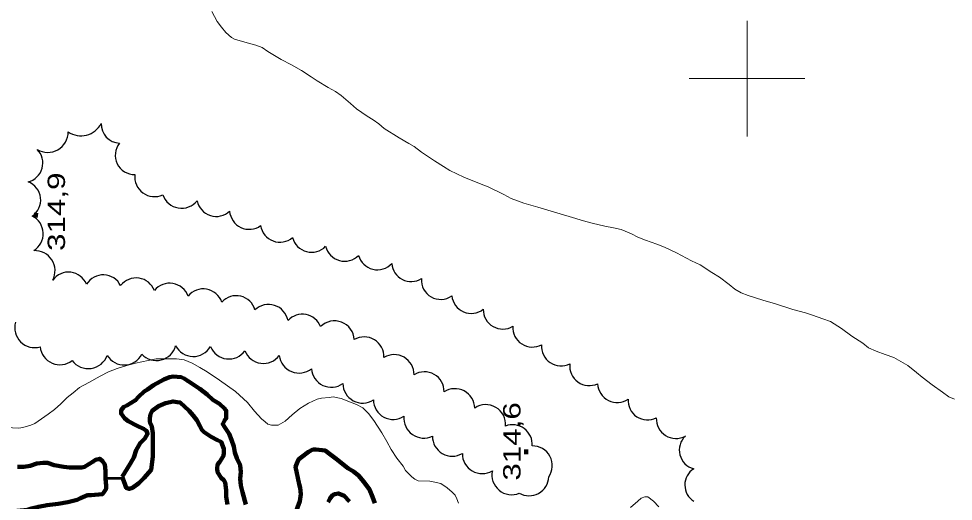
# Model space of a CAD drawing. Extents: x 240591 to 242335, y 5323482 to 5326937.
# Drawn here: x 240674 to 240835.7, y 5324326.9 to 5324410.4 of the extents above; entities that cross this region are included whole.
import ezdxf
from ezdxf.enums import TextEntityAlignment as Align

# ---------------------------------------------------------------- set-up
doc = ezdxf.new("R2010")
doc.units = 0
doc.header["$LTSCALE"] = 1.2
doc.linetypes.add('DASH_DOUBLE_DOT', pattern=[9.2, 5, -1.2, 0.3, -1.2, 0.3, -1.2])
doc.linetypes.add('LONG_DASHED', pattern=[7.5, 6, -1.5])
for name, color, linetype, lineweight in [('2', 7, 'Continuous', 13), ('3', 7, 'Continuous', 140), ('4', 7, 'DASH_DOUBLE_DOT', 53), ('44', 7, 'Continuous', 25), ('61', 7, 'Continuous', 13)]:
    doc.layers.add(name, color=color, linetype=linetype, lineweight=lineweight)

msp = doc.modelspace()

# ---------------------------------------------------------------- linework, layer by layer
at = {"layer": '2', "linetype": 'LONG_DASHED'}
msp.add_lwpolyline([(240835.9, 5324344.6), (240834.9, 5324345), (240833.8, 5324345.8), (240832, 5324347.1), (240830.3, 5324348.4), (240829.3, 5324349.2), (240827.8, 5324350.4), (240826.6, 5324351.1), (240825.4, 5324351.8), (240823.9, 5324352.3), (240822.3, 5324352.9), (240821, 5324353.5), (240820, 5324354.3), (240818.1, 5324355.5), (240816.3, 5324356.8), (240814.4, 5324358), (240813.1, 5324358.5), (240811.3, 5324359.1), (240810.1, 5324359.5), (240807.9, 5324360.1), (240804.9, 5324361.1), (240802.7, 5324361.7), (240800.2, 5324362.5), (240799, 5324363), (240797.9, 5324363.6), (240796.9, 5324364.4), (240795.2, 5324365.7), (240793.9, 5324366.5), (240791.9, 5324367.8), (240790.4, 5324368.5), (240787.8, 5324369.9), (240785.7, 5324370.9), (240784.4, 5324371.4), (240782.4, 5324372.1), (240781.1, 5324372.6), (240780, 5324373.2), (240778.2, 5324373.9), (240776.9, 5324374.2), (240775.4, 5324374.5), (240773.2, 5324375), (240771.7, 5324375.4), (240769.2, 5324376.2), (240766.7, 5324376.9), (240763.8, 5324377.8), (240761.4, 5324378.5), (240759.2, 5324379.3), (240757.9, 5324380), (240755.2, 5324381.3), (240753.7, 5324381.9), (240751, 5324383), (240748.6, 5324384.1), (240747.5, 5324384.8), (240745.9, 5324385.8), (240743.7, 5324387.3), (240742.4, 5324388.3), (240741.5, 5324388.8), (240739.8, 5324389.8), (240737.2, 5324391.4), (240736.3, 5324392.2), (240735.3, 5324392.9), (240734.3, 5324393.5), (240732.4, 5324394.8), (240731.4, 5324395.7), (240730.6, 5324396.4), (240729.8, 5324397.1), (240728.8, 5324397.8), (240727.5, 5324398.5), (240725.6, 5324399.6), (240724.6, 5324400.3), (240722.9, 5324401.4), (240721.2, 5324402.4), (240719.4, 5324403.3), (240717.1, 5324404.7), (240716.1, 5324405.4), (240715, 5324405.8), (240713.9, 5324406.1), (240711.3, 5324406.8), (240710.8, 5324407.1), (240709.8, 5324408), (240709.1, 5324408.9), (240708.3, 5324409.9), (240707.4, 5324411.6)], dxfattribs=at)
at = {"layer": '2'}
for points in [[(240750.1, 5324326.6), (240749.8, 5324327.4), (240749.5, 5324328), (240749, 5324328.5), (240748.1, 5324329.3), (240747, 5324330), (240745.7, 5324330.3), (240745.1, 5324330.4), (240743.1, 5324330.5), (240742.5, 5324330.8), (240742, 5324331.2), (240740.9, 5324332.3), (240740.5, 5324333), (240739.4, 5324334.4), (240738.4, 5324335.9), (240737.7, 5324337.3), (240736.8, 5324338.8), (240735.4, 5324340.9), (240734.5, 5324342.1), (240733.5, 5324343.1), (240732.4, 5324343.7), (240731.4, 5324344.1), (240729.8, 5324344.7), (240728.4, 5324345), (240727.7, 5324344.9), (240726.4, 5324344.8), (240725.6, 5324344.6), (240724.1, 5324343.9), (240722.6, 5324343), (240721.3, 5324341.9), (240720.1, 5324340.8), (240718.9, 5324340.1), (240718.4, 5324340.1), (240717.7, 5324340.1), (240717.1, 5324340.3), (240716.6, 5324340.7), (240716, 5324341.2), (240714.8, 5324342.5), (240713.6, 5324344), (240712.2, 5324345.3), (240711.5, 5324345.9), (240710.1, 5324346.9), (240708.7, 5324347.9), (240706.6, 5324349.3), (240705.3, 5324350.1), (240704, 5324350.8), (240702.6, 5324351.4), (240701.3, 5324351.6), (240700.6, 5324351.6), (240697.8, 5324351.6), (240696.4, 5324351.3), (240694.2, 5324350.8), (240692.7, 5324350.4), (240691, 5324349.9), (240689.5, 5324349.3), (240688.1, 5324348.6), (240686.1, 5324347.5), (240684.5, 5324346.6), (240683.4, 5324345.7), (240682.4, 5324344.9), (240681.3, 5324343.8), (240680.2, 5324342.8), (240679.1, 5324342), (240676.8, 5324340.4), (240676.1, 5324340.1), (240674.7, 5324339.7), (240674, 5324339.6), (240671.8, 5324339.7)], [(240784.7, 5324326), (240783.8, 5324327), (240782.8, 5324327.7), (240782.3, 5324327.7), (240781.7, 5324327.5), (240781.1, 5324327), (240779.8, 5324325.9)]]:
    msp.add_lwpolyline(points, dxfattribs=at)
at = {"layer": '3'}
for p, q in [((240676.9, 5324376), (240677, 5324376.8)), ((240761.8, 5324335.1), (240761.8, 5324335.9))]:
    msp.add_line(p, q, dxfattribs=at)
at = {"layer": '4'}
msp.add_line((240692, 5324330.9), (240689, 5324330.9), dxfattribs=at)
at = {"layer": '4', "linetype": 'Continuous', "lineweight": 90}
msp.add_line((240692, 5324330.9), (240691.9, 5324331.2), dxfattribs=at)
for points in [[(240691.9, 5324331.2), (240693.3, 5324333.4), (240693.9, 5324334.5), (240694.3, 5324335.8), (240695, 5324337), (240695.8, 5324337.8), (240696.3, 5324338.6), (240696.1, 5324339.1), (240695.6, 5324339.5), (240694.5, 5324340), (240692.9, 5324340.8), (240692.3, 5324341.3), (240691.7, 5324342.1), (240691.7, 5324342.7), (240692.2, 5324343.3), (240692.7, 5324343.5), (240694.2, 5324344.4), (240694.7, 5324345), (240695.7, 5324345.9), (240696.3, 5324346.3), (240697.3, 5324347), (240699.1, 5324348), (240700.1, 5324348.4), (240700.7, 5324348.5), (240702.1, 5324348.4), (240702.6, 5324348.2), (240703.3, 5324347.7), (240705.3, 5324346.4), (240706.6, 5324345.4), (240707.6, 5324344.5), (240708.7, 5324343.8), (240709.6, 5324343), (240709.9, 5324342.6), (240709.9, 5324341.9), (240709.9, 5324341.3), (240709.6, 5324340.9), (240709.3, 5324340.3), (240709.6, 5324339.8), (240710.4, 5324338.6), (240710.8, 5324337.6), (240711.2, 5324336.4), (240711.4, 5324335.4), (240711.7, 5324334.4), (240712.3, 5324333.2), (240712.4, 5324332), (240712.3, 5324330.9), (240712.4, 5324329.7), (240712.7, 5324328.5), (240713.3, 5324326.4)], [(240710.1, 5324326.4), (240709.9, 5324327.7), (240709.9, 5324328.9), (240709.7, 5324330.2), (240709.5, 5324330.6), (240709, 5324331), (240708.4, 5324332), (240708.3, 5324332.6), (240708.4, 5324333.3), (240708.7, 5324333.7), (240709.4, 5324334.8), (240709.5, 5324335.3), (240709.5, 5324336), (240709, 5324337.2), (240708.4, 5324337.5), (240707.3, 5324338.1), (240706.1, 5324338.9), (240705.7, 5324339.3), (240705.3, 5324340), (240704.8, 5324341), (240704.2, 5324341.8), (240703.5, 5324342.6), (240701.9, 5324344), (240701.4, 5324344.1), (240700.7, 5324344.2), (240699.4, 5324343.9), (240698.2, 5324343.4), (240697.1, 5324342.6), (240696.8, 5324342), (240696.7, 5324341.3), (240696.7, 5324340.6), (240697, 5324339.9), (240697.2, 5324338.7), (240697.2, 5324337.6), (240697.2, 5324334.7), (240696.9, 5324332.4), (240696.5, 5324331.9), (240695.7, 5324331), (240694.8, 5324330.1), (240693.7, 5324329.3), (240693.1, 5324329.1), (240692.6, 5324329.3), (240692.4, 5324329.8), (240692, 5324330.9)], [(240721.8, 5324324.8), (240722.6, 5324327), (240722.8, 5324328.2), (240722.7, 5324329.3), (240722.5, 5324329.9), (240721.9, 5324332.9), (240722.1, 5324333.5), (240722.4, 5324334.2), (240722.9, 5324334.6), (240724.1, 5324335.5), (240724.9, 5324335.9), (240725.4, 5324335.9), (240726.5, 5324335.8), (240727, 5324335.7), (240728, 5324335), (240728.9, 5324334.3), (240730.9, 5324332.7), (240731.9, 5324332.1), (240732.8, 5324331.4), (240733.7, 5324330.3), (240734.7, 5324329), (240735.2, 5324327.7), (240735.6, 5324326.6)], [(240689, 5324330.9), (240689, 5324332.2), (240688.9, 5324333.3), (240688.5, 5324333.9), (240688, 5324334.3), (240687.3, 5324334.1), (240686.9, 5324333.8), (240685.4, 5324332.9), (240684.9, 5324332.8), (240684.3, 5324332.8), (240682.8, 5324332.8), (240681.8, 5324332.9), (240680.1, 5324333.2), (240679, 5324333.6), (240678.2, 5324333.6), (240677.1, 5324333.5), (240676, 5324333.1), (240674.9, 5324332.9), (240673.8, 5324332.9)], [(240673.7, 5324325.3), (240675.5, 5324325.5), (240676.2, 5324325.7), (240677.4, 5324326), (240678.9, 5324326.3), (240680.8, 5324326.5), (240682.5, 5324326.8), (240684.1, 5324327.2), (240684.7, 5324327.5), (240685.9, 5324328), (240686.5, 5324328), (240688.5, 5324328.2), (240688.8, 5324328.6), (240689.1, 5324329.1), (240689.1, 5324329.6), (240689, 5324330.9)], [(240731.2, 5324326.9), (240730.3, 5324327.9), (240729.3, 5324328.3), (240728.7, 5324328.2), (240728.3, 5324328), (240727.8, 5324327.4), (240727.5, 5324326.8)]]:
    msp.add_lwpolyline(points, dxfattribs=at)
at = {"layer": '44'}
for centre, radius, start, end in [((240684.771, 5324394.08), 3.953, 235.8131, 332.5563), ((240679.028, 5324390.772), 3.523, 238.74894, 0.62543), ((240674.821, 5324385.406), 3.347, 283.94326, 44.70308), ((240702.178, 5324381.044), 3.446, 199.03614, 321.10202), ((240719.176, 5324375.102), 3.373, 188.55134, 310.58656), ((240730.376, 5324371.828), 3.381, 193.64581, 315.31634), ((240688.616, 5324362.705), 3.378, 26.84229, 148.69285), ((240752.275, 5324362.815), 3.385, 186.18728, 307.79742), ((240757.726, 5324360.091), 3.376, 179.1681, 301.10139), ((240676.752, 5324356.948), 3.444, 164.12136, 286.14764), ((240762.845, 5324356.987), 3.382, 176.39228, 298.32353), ((240733.755, 5324351.932), 3.428, 357.96012, 120.01407), ((240681.128, 5324353.991), 3.436, 185.85622, 307.92177), ((240697.816, 5324354.721), 3.444, 223.06135, 344.82638), ((240704.194, 5324355.433), 3.454, 207.83598, 329.50399), ((240710.351, 5324354.983), 3.437, 202.2695, 323.95398), ((240716.326, 5324354.209), 3.431, 201.35491, 323.11476), ((240767.817, 5324353.717), 3.38, 175.02863, 296.78389), ((240686.036, 5324353.406), 3.513, 217.25146, 339.21977), ((240692.251, 5324353.935), 3.427, 211.19069, 332.83177), ((240722.495, 5324352.563), 3.45, 186.88093, 308.66901), ((240728.067, 5324350.083), 3.423, 183.57163, 305.60861), ((240772.69, 5324350.314), 3.372, 173.42428, 295.47779), ((240733.491, 5324347.354), 3.432, 180.91001, 302.79896), ((240738.777, 5324344.528), 3.428, 180.96328, 302.91424), ((240744.056, 5324341.311), 3.433, 174.33367, 296.16731), ((240748.988, 5324338.156), 3.419, 178.75646, 300.82718), ((240754.173, 5324335.16), 3.433, 178.99712, 300.77871)]:
    msp.add_arc(centre, radius, start, end, dxfattribs=at)
for centre, major_axis, ratio, start_param, end_param in [((240691.596, 5324392.194), (1.729, -2.868), 0.999936, 4.146139, 5.6933249), ((240694.045, 5324386.772), (-3.09, -1.309), 0.995455, 5.2080157, 7.4653689), ((240674.455, 5324379.025), (3.324, -0.389), 0.999511, 5.4268805, 7.6123962), ((240697.477, 5324383.022), (-2.271, -2.56), 0.999592, 5.3182618, 7.4442701), ((240708.167, 5324379.559), (-1.015, -3.22), 0.999948, 5.2203021, 7.3432053), ((240713.855, 5324377.339), (-1.805, -2.862), 0.999755, 5.3458341, 7.4732863), ((240674.796, 5324373.193), (3.437, -0.055), 0.998828, 5.2809922, 7.4040437), ((240724.649, 5324373.373), (-0.855, -3.274), 0.999857, 5.2164293, 7.344594), ((240676.809, 5324366.806), (3.37, 0.832), 0.999962, 5.5502974, 7.6720738), ((240736.044, 5324370.349), (-0.807, -3.288), 0.999977, 5.2219122, 7.348391), ((240741.881, 5324368.293), (0.175, -3.358), 0.999203, 4.7324928, 6.7881921), ((240682.603, 5324363.189), (1.186, 3.16), 0.999926, 5.4575438, 7.5859366), ((240694.312, 5324362.18), (-3.126, -1.272), 0.999994, 3.1152951, 5.2441095), ((240700.115, 5324361.263), (0.555, 3.337), 0.999537, 5.2198262, 7.3461554), ((240746.989, 5324365.194), (2.991, -1.509), 0.999856, 3.5357829, 5.7906143), ((240705.93, 5324360.284), (0.582, 3.326), 0.999857, 5.219353, 7.3497107), ((240711.613, 5324359.118), (-2.293, -2.473), 0.999983, 2.5922274, 4.7208381), ((240717.218, 5324357.538), (1.03, 3.273), 0.9998, 5.2172914, 7.3456356), ((240723.057, 5324355.889), (-3.401, -0.081), 0.999375, 3.4927433, 5.5041732), ((240728.633, 5324354.726), (-3.08, 1.466), 0.999437, 3.6370651, 5.9425071), ((240738.954, 5324348.879), (-3.426, -0.039), 0.999995, 3.1159312, 5.2450787), ((240744.161, 5324345.9), (1.986, 2.796), 0.999594, 5.3180254, 7.4472256), ((240749.461, 5324342.986), (1.596, 3.036), 0.999978, 5.2179747, 7.3442306), ((240777.517, 5324347.416), (-1.504, -3.028), 0.99972, 5.21665, 7.3460997), ((240754.813, 5324340.259), (-3.018, 1.56), 0.999439, 3.5279262, 5.7909152), ((240782.764, 5324344.357), (-2.033, -2.66), 0.999083, 5.2829855, 7.4096993), ((240759.424, 5324336.765), (-2.821, 1.923), 0.999435, 3.670206, 5.6779697), ((240787.691, 5324341.214), (-1.795, -2.897), 0.998554, 5.2176518, 7.3408418), ((240791.593, 5324335.797), (-2.894, -1.64), 0.998861, 4.9457538, 7.0849655), ((240762.886, 5324333.12), (-2.278, 2.535), 0.999484, 3.3729359, 5.5679871), ((240759.26, 5324331.486), (2.588, -2.218), 0.999437, 3.6364725, 5.8197583), ((240792.552, 5324329.781), (-0.199, -3.318), 0.99974, 3.7718485, 5.7913327), ((240762.279, 5324331.308), (3.063, 1.496), 0.999751, 3.7365998, 5.7892105)]:
    msp.add_ellipse(centre, major_axis=major_axis, ratio=ratio, start_param=start_param, end_param=end_param, dxfattribs=at)
at = {"layer": '61'}
for points in [[(240800, 5324410), (240800, 5324400), (240800, 5324390)], [(240790, 5324400), (240800, 5324400), (240810, 5324400)]]:
    msp.add_lwpolyline(points, dxfattribs=at)

# ---------------------------------------------------------------- texts
at = {"layer": '3', "width": 1.35}
for s, p in [('314,9', (240682, 5324377)), ('314,6', (240760.8, 5324337.3))]:
    msp.add_text(s, height=3, rotation=90, dxfattribs=at).set_placement(p, align=Align.CENTER)

doc.saveas('drawing.dxf')
